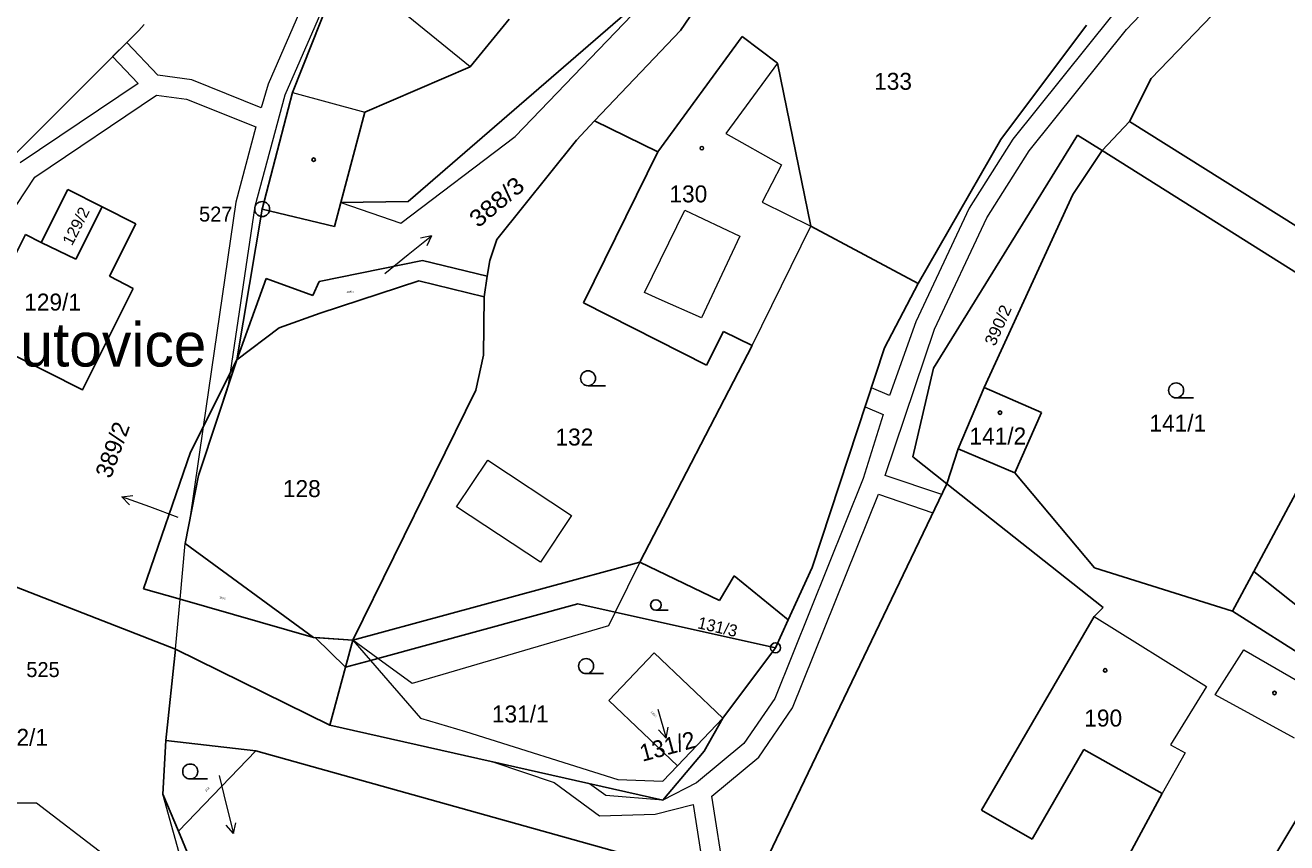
# Model space of a CAD drawing. Extents: x -504006 to -501322, y -1128098 to -1124665.
# Drawn here: x -502675.9 to -502549.5, y -1126613.8 to -1126531.9 of the extents above; entities that cross this region are included whole.
import ezdxf
from ezdxf.enums import TextEntityAlignment as Align

# ---------------------------------------------------------------- set-up
doc = ezdxf.new("R2010")
doc.units = 0
doc.header["$LTSCALE"] = 0.68
for name, color, linetype, lineweight in [('1', 7, 'Continuous', 25), ('13', 7, 'Continuous', 13), ('3', 7, 'Continuous', 25), ('4', 7, 'Continuous', 13), ('5', 7, 'Continuous', 25), ('7', 7, 'Continuous', 13), ('8', 7, 'Continuous', 25)]:
    doc.layers.add(name, color=color, linetype=linetype, lineweight=lineweight)
doc.layers.add('2', color=7, linetype='Continuous')

msp = doc.modelspace()

# ---------------------------------------------------------------- linework, layer by layer
at = {"layer": '1'}
for p, q in [((-502610.27, -1126532.43), (-502600.43, -1126517.88)), ((-502649.16, -1126538.63), (-502644.02, -1126525.7)), ((-502611.07, -1126526.63), (-502637.57, -1126549.58)), ((-502563.11, -1126537.25), (-502552.04, -1126525.68)), ((-502664.57, -1126532.42), (-502664.03, -1126531.82)), ((-502627.44, -1126531.29), (-502631.37, -1126536.07)), ((-502680.89, -1126548.73), (-502664.57, -1126532.42)), ((-502618.89, -1126541.49), (-502610.27, -1126532.43)), ((-502612.54, -1126544.58), (-502604.12, -1126533.03)), ((-502604.12, -1126533.03), (-502600.55, -1126535.7)), ((-502569.59, -1126531.9), (-502578.18, -1126543.35)), ((-502631.37, -1126536.07), (-502641.93, -1126540.6)), ((-502600.55, -1126535.7), (-502597.24, -1126552.03)), ((-502565.3, -1126541.54), (-502563.11, -1126537.25)), ((-502652.2, -1126550.32), (-502649.16, -1126538.63)), ((-502641.93, -1126540.6), (-502644.33, -1126549.66)), ((-502620.71, -1126543.41), (-502618.89, -1126541.49)), ((-502618.89, -1126541.49), (-502612.54, -1126544.58)), ((-502568.05, -1126544.45), (-502565.3, -1126541.54)), ((-502533.04, -1126561.8), (-502565.3, -1126541.54)), ((-502584.95, -1126566.26), (-502570.5, -1126542.91)), ((-502570.5, -1126542.91), (-502568.05, -1126544.45)), ((-502628.7, -1126553.39), (-502620.71, -1126543.41)), ((-502578.18, -1126543.35), (-502586.48, -1126557.78)), ((-502570.99, -1126548.85), (-502568.05, -1126544.45)), ((-502539.8, -1126562.27), (-502568.05, -1126544.45)), ((-502620, -1126559.71), (-502612.54, -1126544.58)), ((-502671.67, -1126548.38), (-502668.24, -1126550.11)), ((-502579.87, -1126568.2), (-502570.99, -1126548.85)), ((-502668.24, -1126550.11), (-502670.88, -1126555.36)), ((-502668.24, -1126550.11), (-502664.85, -1126551.82)), ((-502652.2, -1126550.32), (-502654.75, -1126565.44)), ((-502644.97, -1126552.06), (-502652.2, -1126550.32)), ((-502644.33, -1126549.66), (-502644.97, -1126552.06)), ((-502637.57, -1126549.58), (-502644.33, -1126549.66)), ((-502664.85, -1126551.82), (-502667.49, -1126557.06)), ((-502597.24, -1126552.03), (-502586.48, -1126557.78)), ((-502681.01, -1126562.98), (-502675.91, -1126552.87)), ((-502675.91, -1126552.87), (-502674.34, -1126553.66)), ((-502629.39, -1126555.47), (-502628.7, -1126553.39)), ((-502636.15, -1126555.49), (-502646.49, -1126557.58)), ((-502629.64, -1126557.06), (-502636.15, -1126555.49)), ((-502629.64, -1126557.06), (-502629.39, -1126555.47)), ((-502667.49, -1126557.06), (-502665.11, -1126558.27)), ((-502629.96, -1126559.12), (-502629.64, -1126557.06)), ((-502651.8, -1126557.28), (-502654.75, -1126565.44)), ((-502647.13, -1126558.97), (-502651.8, -1126557.28)), ((-502646.49, -1126557.58), (-502647.13, -1126558.97)), ((-502646.39, -1126560.75), (-502636.5, -1126557.51)), ((-502636.5, -1126557.51), (-502629.96, -1126559.12)), ((-502586.48, -1126557.78), (-502589.84, -1126564.24)), ((-502629.96, -1126559.12), (-502630.04, -1126564.98)), ((-502650.49, -1126562.23), (-502646.39, -1126560.75)), ((-502607.67, -1126565.95), (-502620, -1126559.71)), ((-502654.75, -1126565.44), (-502650.49, -1126562.23)), ((-502605.99, -1126562.58), (-502607.67, -1126565.95)), ((-502603.1, -1126564), (-502605.99, -1126562.58)), ((-502552.84, -1126586.64), (-502539.8, -1126562.27)), ((-502614.37, -1126585.69), (-502603.1, -1126564)), ((-502589.84, -1126564.24), (-502597.1, -1126586.23)), ((-502654.75, -1126565.44), (-502659.38, -1126574.67)), ((-502658.59, -1126577.01), (-502654.75, -1126565.44)), ((-502630.04, -1126564.98), (-502630.78, -1126568.47)), ((-502587, -1126575.14), (-502584.95, -1126566.26)), ((-502630.78, -1126568.47), (-502643.13, -1126593.51)), ((-502582.47, -1126574.35), (-502579.87, -1126568.2)), ((-502579.87, -1126568.2), (-502574.13, -1126570.72)), ((-502574.13, -1126570.72), (-502576.78, -1126576.76)), ((-502659.38, -1126574.67), (-502664.08, -1126588.36)), ((-502582.47, -1126574.35), (-502583.59, -1126577.84)), ((-502576.78, -1126576.76), (-502582.47, -1126574.35)), ((-502583.59, -1126577.84), (-502587, -1126575.14)), ((-502659.9, -1126583.83), (-502658.59, -1126577.01)), ((-502568.81, -1126586.27), (-502576.78, -1126576.76)), ((-502583.59, -1126577.84), (-502602.88, -1126618)), ((-502567.94, -1126590.26), (-502583.59, -1126577.84)), ((-502647.06, -1126593.24), (-502659.9, -1126583.83)), ((-502643.13, -1126593.51), (-502614.37, -1126585.69)), ((-502606.38, -1126589.55), (-502614.37, -1126585.69)), ((-502660.89, -1126594.42), (-502679.2, -1126587.28)), ((-502604.92, -1126587.06), (-502606.38, -1126589.55)), ((-502599.49, -1126591.49), (-502604.92, -1126587.06)), ((-502597.1, -1126586.23), (-502599.49, -1126591.49)), ((-502554.98, -1126590.62), (-502568.81, -1126586.27)), ((-502552.84, -1126586.64), (-502554.98, -1126590.62)), ((-502536.69, -1126599.46), (-502552.84, -1126586.64)), ((-502664.08, -1126588.36), (-502660.42, -1126589.41)), ((-502660.42, -1126589.41), (-502647.06, -1126593.24)), ((-502620.56, -1126589.89), (-502640.61, -1126595.34)), ((-502616.83, -1126590.72), (-502620.56, -1126589.89)), ((-502600.76, -1126594.28), (-502616.83, -1126590.72)), ((-502568.83, -1126591.16), (-502580.14, -1126610.56)), ((-502568.83, -1126591.16), (-502567.94, -1126590.26)), ((-502541.25, -1126599.31), (-502554.98, -1126590.62)), ((-502599.49, -1126591.49), (-502600.76, -1126594.28)), ((-502643.13, -1126593.51), (-502647.06, -1126593.24)), ((-502643.13, -1126593.51), (-502643.86, -1126596.23)), ((-502661.84, -1126603.57), (-502660.89, -1126594.42)), ((-502645.43, -1126602.04), (-502660.89, -1126594.42)), ((-502612.91, -1126594.79), (-502617.45, -1126599.57)), ((-502606.03, -1126601.33), (-502612.91, -1126594.79)), ((-502600.76, -1126594.28), (-502606.03, -1126601.33)), ((-502643.86, -1126596.23), (-502645.43, -1126602.04)), ((-502641.36, -1126595.55), (-502643.86, -1126596.23)), ((-502640.61, -1126595.34), (-502641.36, -1126595.55)), ((-502617.45, -1126599.57), (-502610.57, -1126606.11)), ((-502610.57, -1126606.11), (-502606.03, -1126601.33)), ((-502606.03, -1126601.33), (-502607.91, -1126604.63)), ((-502612.07, -1126609.55), (-502645.43, -1126602.04)), ((-502662.14, -1126608.95), (-502661.84, -1126603.57)), ((-502652.82, -1126604.6), (-502661.84, -1126603.57)), ((-502607.91, -1126604.63), (-502612.07, -1126609.55)), ((-502569.88, -1126604.46), (-502575.04, -1126613.46)), ((-502562.03, -1126608.89), (-502569.88, -1126604.46)), ((-502544.95, -1126605.46), (-502554.24, -1126620.87)), ((-502566.52, -1126617.2), (-502562.03, -1126608.89)), ((-502660.6, -1126612.65), (-502662.14, -1126608.95)), ((-502575.04, -1126613.46), (-502580.14, -1126610.56)), ((-502653.09, -1126630.62), (-502660.6, -1126612.65))]:
    msp.add_line(p, q, dxfattribs=at)
for points in [[(-502670.88, -1126555.36), (-502674.34, -1126553.66), (-502671.67, -1126548.38)], [(-502681.01, -1126562.98), (-502670.2, -1126568.43), (-502665.11, -1126558.27)], [(-502612.36, -1126615.94), (-502652.82, -1126604.6), (-502660.6, -1126612.65)]]:
    msp.add_lwpolyline(points, dxfattribs=at)
at = {"layer": '13'}
for points in [[(-502605.84, -1126617.43), (-502607.14, -1126609.14), (-502602.45, -1126605.25), (-502599.05, -1126600.31), (-502590.46, -1126578.9), (-502584.99, -1126580.75), (-502584.11, -1126578.93), (-502589.79, -1126577.02), (-502584.85, -1126562.37), (-502579.59, -1126551.21), (-502575.36, -1126544.48), (-502565.61, -1126532.33), (-502552.52, -1126518.58)], [(-502645.75, -1126524.36), (-502651.61, -1126537.8), (-502652.3, -1126540.17), (-502659.26, -1126537.36), (-502662.65, -1126536.91), (-502665.77, -1126533.62), (-502667.19, -1126535.03), (-502664.63, -1126537.73), (-502676.45, -1126545.69)], [(-502677.7, -1126551.25), (-502674.99, -1126547.13), (-502662.79, -1126538.91), (-502659.78, -1126539.3), (-502652.84, -1126542.1), (-502654.85, -1126549.63), (-502658.1, -1126572.13), (-502655.39, -1126566.71), (-502652.89, -1126550.03), (-502649.91, -1126538.89), (-502645.38, -1126528.51)], [(-502567.11, -1126531.01), (-502577, -1126543.32), (-502581.35, -1126550.25), (-502586.71, -1126561.61), (-502589.33, -1126569.01), (-502591.16, -1126568.23), (-502591.79, -1126570.14), (-502589.97, -1126570.91), (-502591.98, -1126577.32), (-502600.83, -1126599.35), (-502603.93, -1126603.89), (-502608.69, -1126607.82), (-502612.07, -1126609.55), (-502617.77, -1126609.1), (-502619.4, -1126607.9), (-502629.09, -1126605.72), (-502622.95, -1126607.77), (-502618.41, -1126611.12), (-502612.83, -1126610.97), (-502609.03, -1126609.98), (-502607.93, -1126617.03)]]:
    msp.add_lwpolyline(points, dxfattribs=at)
for points in [[(-502658.59, -1126577.01), (-502655.56, -1126567.89), (-502655.39, -1126566.71), (-502658.1, -1126572.13), (-502659.48, -1126581.63)], [(-502646.89, -1126593.25), (-502643.86, -1126596.23), (-502643.13, -1126593.51)]]:
    msp.add_lwpolyline(points, close=True, dxfattribs=at)
at = {"layer": '3'}
for p, q in [((-502619.553, -1126568.03), (-502617.803, -1126568.03)), ((-502560.623, -1126569.24), (-502558.873, -1126569.24)), ((-502612.755, -1126590.52), (-502611.53, -1126590.52)), ((-502619.743, -1126596.87), (-502617.993, -1126596.87)), ((-502659.413, -1126607.43), (-502657.663, -1126607.43))]:
    msp.add_line(p, q, dxfattribs=at)
for centre, radius in [((-502619.5529, -1126567.2798), 0.75), ((-502560.6229, -1126568.4898), 0.75), ((-502612.755, -1126589.9949), 0.525), ((-502619.7429, -1126596.1198), 0.75), ((-502659.4129, -1126606.6798), 0.75)]:
    msp.add_circle(centre, radius, dxfattribs=at)
at = {"layer": '4'}
for p, q in [((-502631.37, -1126536.07), (-502644.02, -1126525.7)), ((-502626.84, -1126543.07), (-502611.07, -1126526.63)), ((-502600.55, -1126535.7), (-502605.75, -1126542.74)), ((-502649.16, -1126538.63), (-502641.93, -1126540.6)), ((-502638.32, -1126551.74), (-502626.84, -1126543.07)), ((-502605.75, -1126542.74), (-502600.16, -1126545.88)), ((-502600.16, -1126545.88), (-502602.11, -1126549.65)), ((-502644.33, -1126549.66), (-502638.32, -1126551.74)), ((-502613.89, -1126558.69), (-502609.84, -1126550.45)), ((-502609.84, -1126550.45), (-502604.34, -1126553.05)), ((-502602.11, -1126549.65), (-502597.24, -1126552.03)), ((-502603.1, -1126564), (-502597.24, -1126552.03)), ((-502604.34, -1126553.05), (-502608.19, -1126561.21)), ((-502612.42, -1126559.34), (-502613.89, -1126558.69)), ((-502608.19, -1126561.21), (-502612.42, -1126559.34)), ((-502632.72, -1126580.17), (-502629.59, -1126575.47)), ((-502629.59, -1126575.47), (-502621.22, -1126581.04)), ((-502624.31, -1126585.72), (-502632.72, -1126580.17)), ((-502621.22, -1126581.04), (-502624.31, -1126585.72)), ((-502660.42, -1126589.41), (-502659.9, -1126583.83)), ((-502614.37, -1126585.69), (-502616.83, -1126590.72)), ((-502660.89, -1126594.42), (-502660.42, -1126589.41)), ((-502616.83, -1126590.72), (-502617.5, -1126592.08)), ((-502568.83, -1126591.16), (-502557.59, -1126598.16)), ((-502617.5, -1126592.08), (-502637.16, -1126597.86)), ((-502643.13, -1126593.51), (-502641.36, -1126595.55)), ((-502640.61, -1126595.34), (-502643.13, -1126593.51)), ((-502556.72, -1126599.01), (-502553.84, -1126594.48)), ((-502553.84, -1126594.48), (-502546.08, -1126598.99)), ((-502641.36, -1126595.55), (-502636.35, -1126601.33)), ((-502637.16, -1126597.86), (-502640.61, -1126595.34)), ((-502557.59, -1126598.16), (-502561.18, -1126604.01)), ((-502548.78, -1126603.34), (-502556.72, -1126599.01)), ((-502636.35, -1126601.33), (-502631.83, -1126602.68)), ((-502631.83, -1126602.68), (-502616.57, -1126607.49)), ((-502559.73, -1126604.82), (-502562.03, -1126608.89)), ((-502561.18, -1126604.01), (-502559.73, -1126604.82)), ((-502612.04, -1126607.65), (-502610.57, -1126606.11)), ((-502616.57, -1126607.49), (-502612.04, -1126607.65)), ((-502674.8, -1126609.85), (-502679.44, -1126609.85)), ((-502668.1, -1126615), (-502674.8, -1126609.85)), ((-502659, -1126620.2), (-502662.14, -1126608.95))]:
    msp.add_line(p, q, dxfattribs=at)
at = {"layer": '5'}
for centre in [(-502608.1468, -1126544.2192), (-502647.0468, -1126545.3792), (-502578.2668, -1126570.7192), (-502567.7368, -1126596.5492), (-502550.7668, -1126598.8092)]:
    msp.add_circle(centre, 0.175, dxfattribs=at)
at = {"layer": '7'}
for p, q in [((-502635.238, -1126553.001), (-502636.331, -1126553.243)), ((-502666.26, -1126579.144), (-502665.49, -1126579.957)), ((-502611.723, -1126603.325), (-502611.518, -1126602.224)), ((-502655.074, -1126612.902), (-502654.83, -1126611.809))]:
    msp.add_line(p, q, dxfattribs=at)
for points in [[(-502639.9, -1126556.79), (-502637.57, -1126554.89), (-502635.238, -1126553.001), (-502635.701, -1126554.021)], [(-502660.63, -1126581.22), (-502663.44, -1126580.17), (-502666.26, -1126579.144), (-502665.148, -1126579.016)], [(-502612.55, -1126600.44), (-502611.723, -1126603.325), (-502612.48, -1126602.5)], [(-502656.51, -1126607.08), (-502655.8, -1126609.99), (-502655.074, -1126612.902), (-502655.802, -1126612.051)]]:
    msp.add_lwpolyline(points, dxfattribs=at)
at = {"layer": '8'}
for centre, radius in [((-502652.2, -1126550.3198), 0.75), ((-502652.2, -1126550.3198), 0.03), ((-502600.76, -1126594.2799), 0.5), ((-502600.76, -1126594.2799), 0.0303)]:
    msp.add_circle(centre, radius, dxfattribs=at)

# ---------------------------------------------------------------- texts
at = {"layer": '2'}
for s, height, p in [('133', 1.7, (-502588.989, -1126538.375)), ('130', 1.7, (-502609.499, -1126549.655)), ('129/1', 1.7, (-502673.2, -1126560.495)), ('388/3', 0.2, (-502643.389, -1126558.72)), ('141/1', 1.7, (-502560.46, -1126572.615)), ('141/2', 1.7, (-502578.49, -1126573.915)), ('132', 1.7, (-502620.919, -1126574.015)), ('128', 1.7, (-502648.229, -1126579.185)), ('131/1', 1.7, (-502626.34, -1126601.765)), ('190', 1.7, (-502567.929, -1126602.175))]:
    msp.add_text(s, height=height, dxfattribs=at).set_placement(p, align=Align.CENTER)
for s, height, rotation, width, p in [('388/3', 1.7, 40, 1.1, (-502628.1584, -1126550.2617)), ('129/2', 1.139, 63, 1.05, (-502670.3484, -1126552.2875)), ('390/2', 1.2, 66, 1.05, (-502577.9205, -1126562.207)), ('131/2', 0.2, 316, 1.1, (-502613.0285, -1126601.0101)), ('212', 0.2, 46, 1.2, (-502657.6392, -1126608.5385))]:
    msp.add_text(s, height=height, rotation=rotation, dxfattribs=dict(at, width=width)).set_placement(p, align=Align.CENTER)
msp.add_text('389/2', height=1.7, rotation=70, dxfattribs=at).set_placement((-502665.4261, -1126572.0614), align=Align.RIGHT)
for s, height, rotation, p in [('389/2', 0.2, 344, (-502656.1991, -1126589.402)), ('131/3', 1.2, 347, (-502606.6985, -1126592.7672))]:
    msp.add_text(s, height=height, rotation=rotation, dxfattribs=at).set_placement(p, align=Align.CENTER)
msp.add_text('392/1', height=1.7, dxfattribs=at).set_placement((-502679.35, -1126604.105))
msp.add_text('131/2', height=1.7, rotation=15, dxfattribs=at).set_placement((-502614.108, -1126605.709))
at = {"layer": '7'}
msp.add_text('Blahutovice', height=4.4, dxfattribs=at).set_placement((-502673, -1126566.1), align=Align.CENTER)
at = {"layer": '8'}
for s, p in [('527', (-502655.179, -1126551.575)), ('525', (-502672.489, -1126597.217))]:
    msp.add_text(s, height=1.5, dxfattribs=at).set_placement(p, align=Align.RIGHT)

doc.saveas('drawing.dxf')
